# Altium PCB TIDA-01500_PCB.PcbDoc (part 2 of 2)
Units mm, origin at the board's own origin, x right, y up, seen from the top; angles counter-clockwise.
Board outline 177.8 x 50.8 mm, 2 copper layers (Top Layer, Bottom Layer), stack 1.575 mm thick; 57 components, 28 nets, 152 pads, 175 vias.
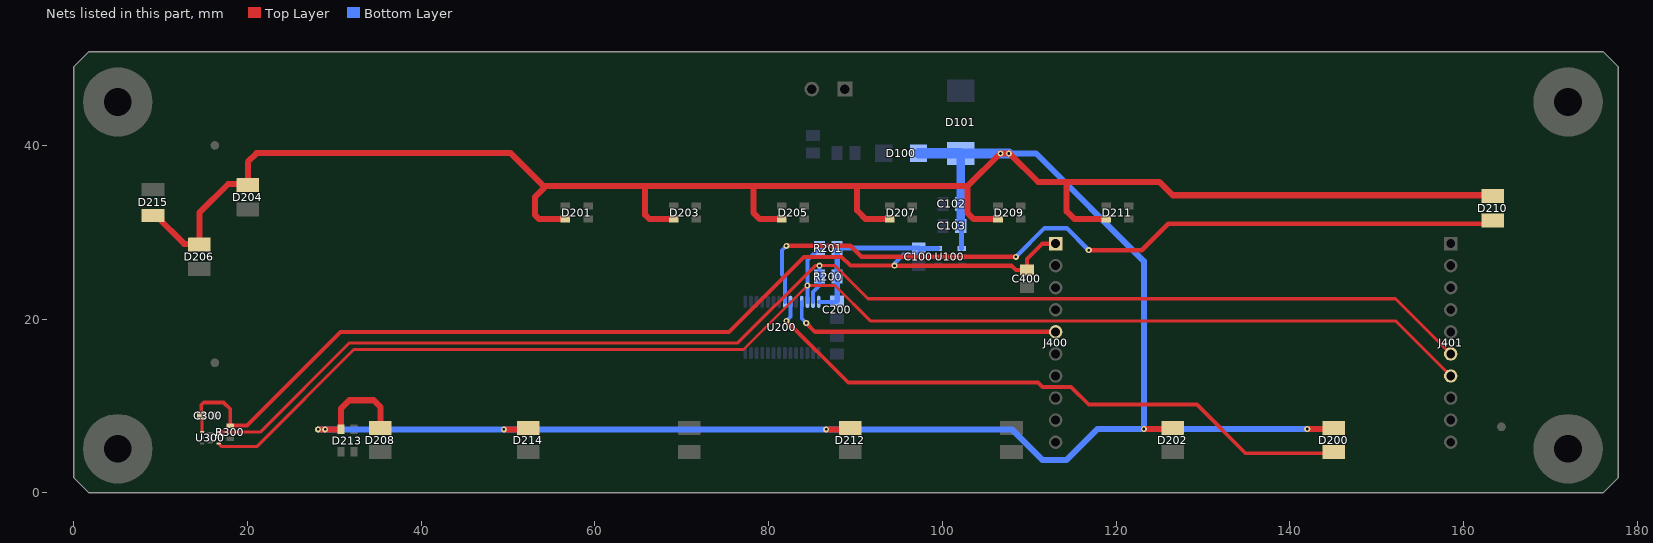
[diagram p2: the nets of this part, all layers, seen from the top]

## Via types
v1: diameter 0.7, hole 0.3, Top Layer to Bottom Layer, 174 vias
v2: diameter 0.5, hole 0.2, Top Layer to Bottom Layer, 1 vias

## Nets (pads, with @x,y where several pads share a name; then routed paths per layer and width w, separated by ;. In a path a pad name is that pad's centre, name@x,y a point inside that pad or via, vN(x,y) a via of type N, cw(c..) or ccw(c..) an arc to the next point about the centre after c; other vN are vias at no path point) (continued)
OUT14: D210.2 U200.22 | length 92.8
  Top Layer w0.5: v1(82.042,28.448) 89.408,28.448 90.678,27.178 v1(108.458,27.178) ; v1(116.84,27.94) 122.936,27.94 125.984,30.988 D210.2@162.294,30.988 ; D210.2@162.572,31.266 D210.2@164.072,31.266
  Bottom Layer w0.45: U200.22@81.859,22 81.859,24.821 81.534,25.146 81.534,27.94 v1(82.042,28.448)
  Bottom Layer w0.5: v1(108.458,27.178) 111.76,30.48 114.3,30.48 v1(116.84,27.94)
OUT15: D200.2 U200.23 | length 72.4
  Top Layer w0.45: v1(82.042,19.812) 89.154,12.7 110.998,12.7 111.506,12.192 114.808,12.192 116.84,10.16 129.286,10.16 134.874,4.572 D200.2@144.272,4.572
  Top Layer w0.5: D200.2@144.284,4.519 D200.2@145.784,4.519
  Bottom Layer w0.45: v1(82.042,19.812) 82.509,20.279 U200.23@82.509,22
RESET: J400.5 U200.25 | length 31.8
  Top Layer w0.5: v1(84.328,19.558) 85.344,18.542 J400.5@113.03,18.542
  Bottom Layer w0.45: U200.25@83.809,22 83.809,20.077 v1(84.328,19.558)
SCL: J401.7 R201.1 U200.26 U300.4 | length 160.7
  Top Layer w0.35: U300.4@16.698,5.7 17.064,5.334 21.082,5.334 32.258,16.51 77.093,16.51 v1(84.459,23.876) 87.63,23.876 91.694,19.812 152.146,19.812 J401.7@158.496,13.462
  Bottom Layer w0.45: U200.26@84.459,22 v1(84.459,23.876) 84.459,26.801 R201.1@85.852,28.194
SDA: J401.6 R200.1 U200.27 U300.6 | length 158.4
  Top Layer w0.35: U300.6@16.698,7 21.478,7 31.75,17.272 76.454,17.272 85.344,26.162 v1(85.852,26.162) 87.63,26.162 91.44,22.352 152.146,22.352 J401.6@158.496,16.002
  Bottom Layer w0.45: U200.27@85.109,22 85.109,23.133 85.852,23.876 R200.1@85.852,24.892 v1(85.852,26.162)
V_SUPPLY: C102.1 C103.1 D100.1 D101.1 D200.1 D201.4 D202.1 D203.4 D204.1 D205.4 D206.1 D207.4 D208.1 D209.4 D210.1 D211.4 D212.1 D213.4 D214.1 D215.1 U100.1 | length 410.9
  Top Layer w0.254: D214.1@51.374,7.319 D214.1@51.574,7.519 ; D212.1@88.458,7.319 D212.1@88.658,7.519 ; D202.1@125.718,7.366 D202.1@125.742,7.342 ; D200.1@144.131,7.366 D200.1@144.284,7.519
  Top Layer w0.7: D215.1@9.144,31.936 9.466,31.936 12.724,28.678 14.478,28.678 14.478,32.258 17.78,35.56 20.066,35.56 20.066,38.1 21.082,39.116 50.292,39.116 54.102,35.306 54.356,35.306 ; v1(28.147,7.319) v1(28.956,7.319) D213.4@30.77,7.319 30.77,9.688 31.75,10.668 34.544,10.668 35.306,9.906 D208.1@35.306,7.496 ; v1(49.53,7.319) D214.1@51.374,7.319 ; D201.4@56.612,31.508 53.582,31.508 53.086,32.004 53.086,34.036 54.356,35.306 ; D203.4@69.058,31.508 66.282,31.508 65.786,32.004 65.786,35.306 ; D205.4@81.504,31.508 78.982,31.508 78.232,32.258 78.232,35.306 ; v1(86.614,7.319) D212.1@88.458,7.319 ; D207.4@93.95,31.508 91.174,31.508 90.17,32.512 90.17,35.306 ; D209.4@106.396,31.508 103.62,31.508 102.87,32.258 102.87,35.306 ; v1(106.68,39.072) v1(107.652,39.072) ; v1@106.68,39.116 102.87,35.306 ; v1@107.696,39.116 110.998,35.814 114.3,35.814 ; D211.4@118.842,31.508 115.216,31.508 114.3,32.424 114.3,35.814 ; v1(123.19,7.366) D202.1@125.718,7.366 ; v1(141.986,7.366) D200.1@144.131,7.366 ; D210.1@162.572,34.266 126.516,34.266 124.968,35.814 114.3,35.814 ; 54.356,35.306 65.786,35.306 ; 65.786,35.306 78.232,35.306 ; 78.232,35.306 90.17,35.306 ; 90.17,35.306 102.87,35.306
  Bottom Layer w0.254: D101.1@102.064,39.116 D101.1@102.108,39.072 ; C103.1@102.108,30.734 C103.1@102.205,30.637
  Bottom Layer w0.6: U100.1@102.205,28.128 C103.1@102.205,30.637
  Bottom Layer w0.7: v1(28.147,7.319) v1(28.956,7.319) v1(49.53,7.319) v1(86.614,7.319) 107.997,7.319 111.506,3.81 114.3,3.81 117.856,7.366 v1(123.19,7.366) ; v1(107.652,39.072) 110.788,39.072 123.19,26.67 v1(123.19,7.366) ; v1(141.986,7.366) v1(123.19,7.366)
  Bottom Layer w1: C103.1@102.108,30.734 D101.1@102.108,39.072
  Bottom Layer w1.2: D100.1@97.25,39.116 D101.1@102.064,39.116 ; D101.1@102.108,39.072 v1(106.68,39.072) v1(107.652,39.072)
VCC: C100.1 C200.1 C300.1 C400.1 J400.1 R200.2 R201.2 R300.1 U100.5 U200.28 U300.1 | length 138.3
  Top Layer w0.35: U300.1@14.798,7 C300.1@14.798,8.786
  Top Layer w0.45: C300.1@14.694,8.89 14.694,10.122 14.986,10.414 17.272,10.414 18.034,9.652 R300.1@18.034,7.75 19.942,7.75 30.734,18.542 75.438,18.542 84.074,27.178 88.392,27.178 89.408,26.162 v1(94.488,26.162)
  Top Layer w0.5: v1(94.488,26.162) 107.95,26.162 108.458,25.654 C400.1@109.728,25.654 109.728,26.924 111.506,28.702 J400.1@113.03,28.702
  Bottom Layer w0.254: C200.1@87.786,22 C200.1@87.884,22.098 ; C100.1@97.274,27.678 97.274,28.128 C100.1@97.274,28.194
  Bottom Layer w0.45: U200.28@85.759,22 C200.1@87.786,22 ; v1(94.488,26.162) 94.488,26.416 95.504,27.432 97.028,27.432 C100.1@97.274,27.678
  Bottom Layer w0.6: C200.1@87.884,22.098 R201.2@87.884,28.194 C100.1@97.274,28.194 ; C100.1@97.274,28.128 U100.5@99.455,28.128
pads on no net: D201.1 D201.3 D203.1 D203.3 D205.1 D205.3 D207.1 D207.3 D209.1 D209.3 D211.1 D211.3 D213.1 D213.3 FID1.1 FID2.1 FID3.1 H1.1 H2.1 H3.1 H4.1 H5.0 H6.0 H7.0 H8.0 J400.2 J400.3 J400.4 J400.7 J400.8 J400.9 J401.2 J401.3 J401.4 J401.5 J401.8 J401.9 J401.10 LBL1.0 U100.3

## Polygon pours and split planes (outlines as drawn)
GND on Bottom Layer "Bottom Layer-No Net" (solid, remove dead copper, pour order 2): 0.254,49.53 1.27,50.546 176.53,50.546 177.292,49.784 177.292,1.016 176.53,0.254 1.27,0.254 0.254,1.27
GND on Top Layer "Bottom Layer-No Net" (solid, remove dead copper, pour order 4): 0.254,49.53 1.27,50.546 176.53,50.546 177.292,49.784 177.292,1.016 176.53,0.254 1.27,0.254 0.254,1.27

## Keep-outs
Keep-Out Layer:
  text ".Layer_Name" at 14.656,-21.806 h1.52

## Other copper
Top Layer:
  region: 31.242,2.794 31.242,5.334 29.972,5.334 29.972,2.794
  region net OUT4: 33.02,2.794 33.02,5.334 31.75,5.334 31.75,2.794
  region: 33.02,6.604 33.02,9.144 31.75,9.144 31.75,6.604
  region net V_SUPPLY: 31.242,6.604 31.242,9.144 29.972,9.144 29.972,6.604
  rectangle: 120.904,30.734 123.444,32.004
  rectangle net OUT11: 96.012,32.512 98.552,33.782
  rectangle: 116.84,32.512 119.38,33.782
  rectangle: 108.458,30.734 110.998,32.004
  rectangle net OUT12: 108.458,32.512 110.998,33.782
  rectangle: 104.394,32.512 106.934,33.782
  rectangle: 96.012,30.734 98.552,32.004
  rectangle net OUT13: 120.904,32.512 123.444,33.782
  rectangle: 91.948,32.512 94.488,33.782
  rectangle: 83.566,30.734 86.106,32.004
  rectangle net OUT8: 58.674,32.512 61.214,33.782
  rectangle: 79.502,32.512 82.042,33.782
  rectangle: 71.12,30.734 73.66,32.004
  rectangle net OUT9: 71.12,32.512 73.66,33.782
  rectangle: 67.056,32.512 69.596,33.782
  rectangle: 58.674,30.734 61.214,32.004
  rectangle net OUT10: 83.566,32.512 86.106,33.782
  rectangle net V_SUPPLY: 116.84,30.734 119.38,32.004
  rectangle net V_SUPPLY: 104.394,30.734 106.934,32.004
  rectangle net V_SUPPLY: 91.948,30.734 94.488,32.004
  rectangle net V_SUPPLY: 79.502,30.734 82.042,32.004
  rectangle net V_SUPPLY: 67.056,30.734 69.596,32.004
  rectangle net V_SUPPLY: 54.61,30.734 57.15,32.004
  rectangle: 54.61,32.512 57.15,33.782
  text ".Layer_Name" at 14.656,-21.806 h1.52
Bottom Layer:
  text ".Layer_Name" at 14.656,-21.806 h1.52

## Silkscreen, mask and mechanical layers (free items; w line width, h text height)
Top Overlay:
  region: 105.41,23.622 97.79,23.622 97.79,21.082 105.41,21.082
  text "'.PRJ_Number' - '.PCB_Rev'" at 57.15,23.368 h2.75
  text ".Layer_Name" at 14.656,-21.806 h1.52
Bottom Overlay:
  text ".Layer_Name" at 14.656,-21.806 h1.52
Top Paste:
  text ".Layer_Name" at 14.656,-21.806 h1.52
Bottom Paste:
  text ".Layer_Name" at 14.656,-21.806 h1.52
Top Solder:
  text ".Layer_Name" at 14.656,-21.806 h1.52
  text ".Layer_Name" at 14.656,-21.806 h1.52
Bottom Solder:
  text ".Layer_Name" at 14.656,-21.806 h1.52
Drill Guide:
  text ".Layer_Name" at 14.656,-21.806 h1.52
M1 Board Outline:
  the board outline again, w0.254
  text ".Layer_Name" at 14.656,-21.806 h1.52
M2 Board Dimensions:
  rectangle: 0,-6.985 3.175,-3.81
  rectangle: 3.175,-10.16 12.7,-6.985
  lines w0.178: 0,-6.985 25.4,-6.985 ; 3.175,-10.16 3.175,-3.81 ; 6.35,-10.16 6.35,-3.81 ; 12.7,-10.16 12.7,-3.81 ; 19.05,-10.16 19.05,-3.81 ; 0,-10.16 25.4,-10.16 25.4,-3.81 0,-3.81 0,-10.16
  text ".Layer_Name" at 14.656,-21.806 h1.52
M3 3D STEP Top:
  lines w0.254: 7.643,34.973 10.642,34.975 10.642,31.573 ; 7.642,34.975 7.642,31.573 10.642,31.575 ; 12.978,25.477 12.978,28.878 ; 12.979,25.477 15.978,25.478 15.978,28.878 12.979,28.877 ; 18.566,35.736 21.565,35.737 ; 18.566,35.737 18.566,32.336 21.565,32.337 ; 21.566,32.336 21.566,35.737 ; 50.824,7.719 53.823,7.72 ; 50.824,7.72 50.824,4.319 53.823,4.32 ; 53.824,4.319 53.824,7.72 ; 56.211,30.759 59.613,30.759 ; 56.213,30.76 56.211,33.759 59.613,33.759 ; 59.611,33.759 59.613,30.76 ; 68.659,30.757 72.06,30.757 ; 68.66,30.759 68.659,33.757 72.06,33.757 ; 69.365,7.719 72.364,7.72 72.365,4.319 ; 69.365,7.72 69.365,4.319 72.364,4.32 ; 72.059,33.757 72.06,30.759 ; 81.105,30.757 84.506,30.757 ; 81.106,30.759 81.105,33.757 84.506,33.757 ; 84.505,33.757 84.506,30.759 ; 87.908,7.719 90.907,7.72 ; 87.908,7.72 87.908,4.319 90.907,4.32 ; 90.908,4.319 90.908,7.72 ; 93.551,30.757 96.952,30.757 ; 93.552,30.759 93.551,33.757 96.952,33.757 ; 96.951,33.757 96.952,30.759 ; 105.997,30.757 109.398,30.757 ; 105.998,30.759 105.997,33.757 109.398,33.757 ; 106.45,7.719 109.449,7.72 ; 106.45,7.72 106.45,4.319 109.449,4.32 ; 109.397,33.757 109.398,30.759 ; 109.45,4.319 109.45,7.72 ; 118.443,30.757 121.844,30.757 ; 118.444,30.759 118.443,33.757 121.844,33.757 ; 121.843,33.757 121.844,30.759 ; 124.992,7.719 127.991,7.72 ; 124.992,7.72 124.992,4.319 127.991,4.32 ; 127.992,4.319 127.992,7.72 ; 143.534,7.719 146.533,7.72 ; 143.534,7.72 143.534,4.319 146.533,4.32 ; 146.534,4.319 146.534,7.72 ; 161.822,31.065 161.822,34.466 ; 161.823,31.065 164.822,31.066 ; 161.823,34.465 164.822,34.466 164.822,31.065 ; 30.021,4.319 30.021,7.72 36.83,7.719 36.83,4.318 30.021,4.319
  text ".Layer_Name" at 14.656,-21.806 h1.52
M4 3D STEP Bottom:
  text ".Layer_Name" at 14.656,-21.806 h1.52
M5 Assembly Top:
  lines w0.254: -7.417,-23.626 160.223,-23.626 ; -7.417,-18.462 160.274,-18.462 ; -7.417,-13.297 -7.417,-28.791 94.31,-28.791 160.274,-28.791 160.274,-13.297 -7.404,-13.297 -7.404,-28.791 32.614,-28.791 ; 55.194,-28.791 55.194,-13.297 ; 87.376,-18.462 87.376,-13.297 ; 108.712,-18.462 108.712,-13.297 ; 124.511,-28.956 124.511,-23.804
  text "COMPONENTS MARKED 'DNP' SHOULD NOT BE POPULATED." at 29.299,-8.09 h1.52
  text "ASSEMBLY VARIANT:" at 29.286,-11.024 h1.52
  text ".VariantName" at 55.601,-11.024 h1.52
  text "PCB VIEWED FROM TOP SIDE" at -5.804,-16.654 h1.52
  text "BOARD #:" at 57.099,-16.654 h1.52
  text ".PRJ_Number" at 70.955,-16.654 h1.52
  text "REV:" at 92.405,-16.654 h1.52
  text ".PCB_Rev" at 99.809,-16.654 h1.52
  text "SVN REV:" at 113.69,-16.654 h1.52
  text ".VersionControl_RevNumber" at 126.543,-16.654 h1.52
  text "TID #:" at 57.099,-21.819 h1.52
  text ".TID" at 70.955,-21.819 h1.52
  text "PLOT NAME =" at -5.804,-27.034 h1.52
  text ".plot_File_Name" at 14.656,-27.034 h1.52
  text "GENERATED    :" at 57.15,-27.034 h1.52
  text ".Print_Date" at 79.235,-27.034 h1.52
  text ".Print_Time" at 97.752,-27.034 h1.52
  text "TEXAS INSTRUMENTS" at 129.87,-27.034 h1.52
M6 Assembly Bottom:
  lines w0.254: -7.429,-18.474 160.261,-18.474 ; -7.379,-23.639 160.261,-23.639 ; 28.334,-28.969 28.334,-23.817 ; 44.133,-18.474 44.133,-13.31 ; 65.468,-18.474 65.468,-13.31 ; 97.65,-28.804 97.65,-13.31 ; 120.231,-28.804 160.249,-28.804 160.249,-13.31 -7.429,-13.31 -7.429,-28.804 58.534,-28.804 160.261,-28.804 160.261,-13.31
  text "COMPONENTS MARKED 'DNP' SHOULD NOT BE POPULATED." at 154.991,-8.077 h1.52
  text ".VariantName" at 128.473,-11.024 h1.52
  text "ASSEMBLY VARIANT:" at 154.864,-11.024 h1.52
  text ".VersionControl_RevNumber" at 26.302,-16.667 h1.52
  text "SVN REV:" at 39.154,-16.667 h1.52
  text ".PCB_Rev" at 53.035,-16.667 h1.52
  text "REV:" at 60.439,-16.667 h1.52
  text ".PRJ_Number" at 81.89,-16.667 h1.52
  text "BOARD #:" at 95.745,-16.667 h1.52
  text "PCB VIEWED FROM BOTTOM SIDE" at 158.648,-16.667 h1.52
  text ".TID" at 81.89,-21.831 h1.52
  text "TID #:" at 95.745,-21.831 h1.52
  text "TEXAS INSTRUMENTS" at 22.974,-27.047 h1.52
  text ".Print_Time" at 55.093,-27.047 h1.52
  text ".Print_Date" at 73.609,-27.047 h1.52
  text "GENERATED    :" at 95.694,-27.047 h1.52
  text ".plot_File_Name" at 138.189,-27.047 h1.52
  text "PLOT NAME =" at 158.648,-27.047 h1.52
M9 Title Sheet:
  drawing of 57 lines, arcs and shapes, not listed
  text "1" at 18.792,204.127 h1.78
  text "2" at 82.182,204.127 h1.78
  text "3" at 145.411,204.127 h1.78
  text "4" at 209.08,204.127 h1.78
  text "5" at 272.555,204.127 h1.78
  text "6" at 336.182,204.127 h1.78
  text "A" at -10.579,175.095 h1.78
  text "A" at 365.341,175.095 h1.78
  text "B" at -10.579,114.643 h1.78
  text "B" at 365.341,114.643 h1.78
  text "C" at -10.579,54.318 h1.78
  text "C" at 365.341,54.318 h1.78
  text "PROJECT TITLE:" at 288.125,7.048 h1.14
  text ".PRJ_Title" at 289.395,3.662 h1.78
  text "DESIGNED FOR:" at 288.125,-0.597 h1.14
  text ".PRJ_Customer" at 289.395,-4.153 h1.78
  text "D" at -10.579,-5.88 h1.78
  text "D" at 365.341,-5.88 h1.78
  text "FILE NAME:" at 288.125,-8.217 h1.14
  text ".PCB_File_Name_No_Path" at 289.395,-11.265 h1.78
  text "Texas Instruments (TI) and/or its licensors do not warrant the accuracy or completeness of this specification" at 161.9,-15.376 h1.14
  text "ENGINEER:" at 288.125,-15.583 h1.14
  text "LAYOUT BY:" at 326.352,-15.583 h1.14
  text "or any information contained therein. TI and/or its licensors do not warrant that this design will meet" at 160.757,-18.237 h1.14
  text ".PRJ_Engineer" at 289.395,-19.52 h1.78
  text ".PCB_Layout" at 327.635,-19.52 h1.78
  text "the specifications, will be suitable for your application or fit for any particular purpose, or will operate in" at 160.757,-21.099 h1.14
  text ".Layer_Name" at 14.656,-21.806 h1.52
  text "ALTIUM DESIGNER VERSION:" at 326.352,-23.457 h1.14
  text "an implementation. TI and/or its licensors do not warrant that the design is production worthy. You should" at 160.757,-23.961 h1.14
  text "completely validate and test your design implementation to confirm the system functionality for your application." at 161.9,-26.822 h1.14
  text ".print_Scale" at 289.395,-26.843 h1.78
  text ".Application_BuildNumber" at 327.635,-26.843 h1.78
  text "1" at 18.792,-32.093 h1.78
  text "2" at 82.182,-32.093 h1.78
  text "3" at 145.411,-32.093 h1.78
  text "4" at 209.08,-32.093 h1.78
  text "5" at 272.555,-32.093 h1.78
  text "6" at 336.182,-32.093 h1.78
M10 Fab Notes:
  drawing of 173 lines, arcs and shapes, not listed
  text "DESIGN INFORMATION" at 314.402,157.505 h1.52
  text "MIN. TRACK WIDTH:" at 298.03,152.933 h1.52
  text "8" at 325.874,152.933 h1.52
  text "MIL" at 329.805,152.933 h1.52
  text "MIN. CLEARANCE:" at 298.03,149.581 h1.52
  text "0.2" at 324.35,149.581 h1.52
  text "mm" at 329.805,149.581 h1.52
  text "MIN. VIA PAD SIZE:" at 298.03,146.228 h1.52
  text "24" at 325.113,146.228 h1.52
  text "MIL" at 329.805,146.228 h1.52
  text "0.05mm (2MIL)" at 315.683,142.628 h1.52
  text "MINIMUM ANNULAR RING" at 289.667,142.52 h1.52
  text "EXTERNAL" at 333.666,142.52 h1.52
  text "PER" at 294.747,139.522 h1.52
  text "IPC-D-275 CLASS 2 LEVEL C" at 300.335,139.522 h1.52
  text "MIL, HOLES" at 338.136,136.67 h1.52
  text "+/-" at 328.168,136.652 h1.52
  text "+/-" at 349.86,136.652 h1.52
  text "REGISTRATION TOLERANCES:" at 289.667,136.525 h1.52
  text "METAL" at 320.142,136.525 h1.52
  text "5" at 334.777,136.525 h1.52
  text "3" at 355.935,136.525 h1.52
  text "MIL" at 358.888,136.525 h1.52
  text "+/-" at 349.86,133.655 h1.52
  text "HOLE SIZE TOLERANCE (UNLESS OTHERWISE SPECIFIED):" at 289.667,133.528 h1.52
  text "3" at 355.935,133.528 h1.52
  text "MIL" at 358.888,133.528 h1.52
  text "MATERIAL:" at 287.768,128.208 h1.52
  text "FR-4 High Tg" at 312.824,124.643 h1.52
  text "FR-408" at 298.462,124.425 h1.52
  text "OTHER" at 336.257,124.425 h1.52
  text "X" at 308.889,124.333 h1.52
  text "62 MIL (1.6mm) +/-10%" at 306.592,120.292 h1.52
  text "THICKNESS:" at 289.667,120.184 h1.52
  text "X" at 303.337,120.184 h1.52
  text "OTHER" at 339.229,120.184 h1.52
  text "TOLERANCE:" at 289.667,116.17 h1.52
  text "X" at 310.986,116.17 h1.52
  text "ANSI IPC-6012 TYPE 3 CLASS 2" at 315.734,116.17 h1.52
  text "OTHER +/-" at 315.734,112.208 h1.52
  text "BOW & TWIST:" at 289.667,108.22 h1.52
  text "X" at 310.986,108.22 h1.52
  text "ANSI IPC-6012 TYPE 3 CLASS 2" at 315.734,108.22 h1.52
  text "OTHER +/-" at 315.734,104.194 h1.52
  text "DRILLING:" at 287.768,100.676 h1.52
  text "REFERENCE:" at 289.667,97.705 h1.52
  text "X" at 306.132,97.705 h1.52
  text "AS SHOWN" at 310.882,97.705 h1.52
  text "X" at 329.018,97.705 h1.52
  text "NC_DRILL FILES" at 332.498,97.705 h1.52
  text "PTH COPPER THICKNESS:" at 289.667,93.691 h1.52
  text "X" at 318.375,93.691 h1.52
  text "20-30 um" at 321.855,93.691 h1.52
  text "OTHER" at 340.067,93.691 h1.52
  text "BOARD FINISH:" at 287.768,89.653 h1.52
  text "SILKSCREEN:" at 291.711,86.656 h1.52
  text "X" at 315.81,86.656 h1.52
  text "TOP" at 319.01,86.656 h1.52
  text "X" at 328.764,86.656 h1.52
  text "BOTTOM" at 331.99,86.656 h1.52
  text "SILKSCREEN COLOR:" at 291.711,82.414 h1.52
  text "X" at 315.783,82.414 h1.52
  text "WHITE" at 319.01,82.414 h1.52
  text "OTHER" at 331.99,82.414 h1.52
  text "X" at 319.111,78.37 h1.52
  text "GREEN" at 322.338,78.37 h1.52
  text "OTHER" at 338.035,78.37 h1.52
  text "SOLDER RESIST COLOR:" at 291.711,78.096 h1.52
  text "X" at 319.111,74.052 h1.52
  text "MATTE" at 322.338,74.052 h1.52
  text "SEMI-GLOSS" at 338.023,74.036 h1.52
  text "IMMERSION GOLD (ENIG)" at 314.718,69.264 h1.52
  text "ENEPIG" at 348.691,69.18 h1.52
  text "SURFACE FINISH:" at 287.768,69.155 h1.52
  text "X" at 309.969,69.155 h1.52
  text "IMM. TIN/SILVER OR EQUIV" at 296.139,65.167 h1.52
  text "OTHER" at 332.498,65.167 h1.52
  text "ARRAY/PANEL:" at 287.768,60.621 h1.52
  text "CUT AND TRIM PER M1 BOARD OUTLINE" at 314.718,60.512 h1.52
  text "N.C. ROUTE" at 314.718,56.658 h1.52
  text "X" at 331.964,56.658 h1.52
  text "V. SCORE" at 336.714,56.658 h1.52
  text "CERTIFICATION:" at 287.768,53.178 h1.52
  text "MATERIALS AND WORKMANSHIP FOR ALL PCBS" at 306.183,53.178 h1.52
  text "TO MEET OR EXCEED THE REQUIREMENTS OF:" at 306.183,50.689 h1.52
  text "X" at 296.696,47.222 h1.52
  text "ANSI IPC-A-600F CLASS ->" at 300.227,47.222 h1.52
  text "X" at 341.859,47.222 h1.52
  text "2" at 344.88,47.222 h1.52
  text "1" at 336.879,47.184 h1.52
  text "3" at 353.872,47.184 h1.52
  text "X" at 317.373,43.171 h1.52
  text "RoHS" at 320.852,43.171 h1.52
  text "OTHER" at 337.22,43.171 h1.52
  text "PER ORDER" at 347.305,43.171 h1.52
  text "ALL BOARDS MUST MEET OR EXCEED UL94-V0 REQUIREMENTS." at 288.468,38.964 h1.52
  text "PCB MUST BEAR THE UL94V-0 UL REGISTERED MATERIAL ID NUMBER" at 288.468,35.916 h1.52
  text "ADDITIONAL REQUIREMENTS:" at 287.768,31.512 h1.52
  text "MICROSECTION:" at 289.667,28.591 h1.52
  text "YES" at 312.673,28.591 h1.52
  text "REQUIRED" at 334.555,24.625 h1.52
  text "BARE BOARD ELEC. TEST:" at 289.667,24.553 h1.52
  text "NONE" at 322.833,24.553 h1.52
  text "X" at 331.329,24.553 h1.52
  text "PER ORDER" at 349.592,24.553 h1.52
  text ".Layer_Name" at 14.656,-21.806 h1.52
M11 Gerber Information:
  lines w0.254: -7.417,-23.626 160.223,-23.626 ; -7.417,-18.462 160.274,-18.462 ; -7.417,-13.297 -7.417,-28.791 94.31,-28.791 160.274,-28.791 160.274,-13.297 -7.404,-13.297 -7.404,-28.791 32.614,-28.791 ; 55.194,-28.791 55.194,-13.297 ; 87.376,-18.462 87.376,-13.297 ; 108.712,-18.462 108.712,-13.297 ; 124.511,-28.956 124.511,-23.804
  text "ALL ARTWORK VIEWED FROM TOP SIDE" at -5.804,-16.654 h1.52
  text "BOARD #:" at 57.099,-16.654 h1.52
  text ".PRJ_Number" at 70.955,-16.654 h1.52
  text "REV:" at 92.405,-16.654 h1.52
  text ".PCB_Rev" at 99.809,-16.654 h1.52
  text "SVN REV:" at 113.69,-16.654 h1.52
  text ".VersionControl_RevNumber" at 126.543,-16.654 h1.52
  text "LAYER NAME =" at -5.804,-21.806 h1.52
  text "TID #:" at 57.099,-21.819 h1.52
  text ".TID" at 70.955,-21.819 h1.52
  text "PLOT NAME =" at -5.804,-27.034 h1.52
  text ".plot_File_Name" at 14.656,-27.034 h1.52
  text "GENERATED    :" at 57.15,-27.034 h1.52
  text ".Print_Date" at 79.235,-27.034 h1.52
  text ".Print_Time" at 97.752,-27.034 h1.52
  text "TEXAS INSTRUMENTS" at 129.87,-27.034 h1.52
M12 Stackup:
  drawing of 191 lines, arcs and shapes, not listed
  text "Layer" at 248.675,198.882 h1.52
  text "Name" at 259.086,198.882 h1.52
  text "Material" at 282.702,198.882 h1.52
  text "Thickness" at 304.54,198.882 h1.52
  text "Constant" at 321.046,198.882 h1.52
  text "Board Layer Stack" at 335.52,198.882 h1.52
  text "1" at 248.675,195.834 h1.52
  text "Top Overlay" at 259.086,195.834 h1.52
  text "2" at 248.675,192.786 h1.52
  text "Top Solder" at 259.086,192.786 h1.52
  text "Solder Resist" at 282.702,192.786 h1.52
  text "0.40mil" at 304.54,192.786 h1.52
  text "3.5" at 321.046,192.786 h1.52
  text "3" at 248.675,189.738 h1.52
  text "Top Layer" at 259.086,189.738 h1.52
  text "Copper" at 282.702,189.738 h1.52
  text "1.40mil" at 304.54,189.738 h1.52
  text "4" at 248.675,186.69 h1.52
  text "Dielectric1" at 259.086,186.69 h1.52
  text "FR-4" at 282.702,186.69 h1.52
  text "59.20mil" at 304.54,186.69 h1.52
  text "4.8" at 321.046,186.69 h1.52
  text "5" at 248.675,183.642 h1.52
  text "Bottom Layer" at 259.086,183.642 h1.52
  text "Copper" at 282.702,183.642 h1.52
  text "1.40mil" at 304.54,183.642 h1.52
  text "6" at 248.675,180.594 h1.52
  text "Bottom Solder" at 259.086,180.594 h1.52
  text "Solder Resist" at 282.702,180.594 h1.52
  text "0.40mil" at 304.54,180.594 h1.52
  text "3.5" at 321.046,180.594 h1.52
  text "7" at 248.675,177.546 h1.52
  text "Bottom Overlay" at 259.086,177.546 h1.52
  text ".Layer_Name" at 14.656,-21.806 h1.52
M13 Component Bodies Top:
  text ".Layer_Name" at 14.656,-21.806 h1.52
M14 Component Bodies Bottom:
  text ".Layer_Name" at 14.656,-21.806 h1.52
M15 Courtyards Top:
  text ".Layer_Name" at 14.656,-21.806 h1.52
M16 Courtyards Bottom:
  text ".Layer_Name" at 14.656,-21.806 h1.52
Drill Drawing:
  circle w0.254: c136.238,70.333 r0.702
  lines w0.254: 135.537,72.789 136.94,72.789 136.94,74.192 135.537,74.192 135.537,72.789 ; 135.537,77.35 136.94,77.35 136.238,75.946 135.537,77.35 ; 135.537,79.455 135.888,79.455 135.888,79.104 136.589,79.104 136.589,79.455 136.94,79.455 136.94,80.157 136.589,80.157 136.589,80.508 135.888,80.508 135.888,80.157 135.537,80.157 135.537,79.455 ; 135.537,82.613 135.888,82.613 136.238,82.262 136.589,82.613 136.94,82.613 136.589,82.964 136.94,83.314 136.589,83.314 136.238,83.665 135.888,83.314 135.537,83.314 135.888,82.964 135.537,82.613
  lines w0.305: 134.264,68.684 216.344,68.684 ; 134.264,84.472 216.344,84.472 ; 142.846,65.526 142.846,87.63 ; 151.279,65.526 151.279,87.63 ; 167.448,65.526 167.448,87.63 ; 174.03,65.526 174.03,87.63 ; 183.559,65.526 183.559,87.63 ; 201.957,65.526 201.957,87.63 ; 134.264,65.526 216.344,65.526 216.344,87.63 134.264,87.63 134.264,65.526
  text "Symbol" at 136.159,85.42 h1.83
  text "Quantity" at 143.793,85.42 h1.83
  text "Finished Hole Size" at 152.226,85.42 h1.83
  text "Plated" at 168.395,85.42 h1.83
  text "Hole Type" at 174.977,85.42 h1.83
  text "Drill Layer Pair" at 184.506,85.42 h1.83
  text "Hole Tolerance" at 202.904,85.42 h1.83
  text "1" at 143.793,82.262 h1.52
  text "7.87mil (0.200mm)" at 152.226,82.262 h1.52
  text "PTH" at 168.395,82.262 h1.52
  text "Round" at 174.977,82.262 h1.52
  text "Top Layer - Bottom Layer" at 184.506,82.262 h1.52
  text "174" at 143.793,79.104 h1.52
  text "11.81mil (0.300mm)" at 152.226,79.104 h1.52
  text "PTH" at 168.395,79.104 h1.52
  text "Round" at 174.977,79.104 h1.52
  text "Top Layer - Bottom Layer" at 184.506,79.104 h1.52
  text "20" at 143.793,75.946 h1.52
  text "40.16mil (1.020mm)" at 152.226,75.946 h1.52
  text "PTH" at 168.395,75.946 h1.52
  text "Round" at 174.977,75.946 h1.52
  text "Top Layer - Bottom Layer" at 184.506,75.946 h1.52
  text "2" at 143.793,72.789 h1.52
  text "43.31mil (1.100mm)" at 152.226,72.789 h1.52
  text "PTH" at 168.395,72.789 h1.52
  text "Round" at 174.977,72.789 h1.52
  text "Top Layer - Bottom Layer" at 184.506,72.789 h1.52
  text "4" at 143.793,69.631 h1.52
  text "125.98mil (3.200mm)" at 152.226,69.631 h1.52
  text "PTH" at 168.395,69.631 h1.52
  text "Round" at 174.977,69.631 h1.52
  text "Top Layer - Bottom Layer" at 184.506,69.631 h1.52
  text "201 Total" at 143.793,66.473 h1.52
  text ".Layer_Name" at 14.656,-21.806 h1.52
M17 Embedded Cavity:
  text ".Layer_Name" at 14.656,-21.806 h1.52
M18 Embedded Assembly:
  text ".Layer_Name" at 14.656,-21.806 h1.52
M19 Embedded Keepout:
  text ".Layer_Name" at 14.656,-21.806 h1.52

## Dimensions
0,-10.16 to 25.4,-10.16 on M2 Board Dimensions
0,0 to 177.8,0 on M2 Board Dimensions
